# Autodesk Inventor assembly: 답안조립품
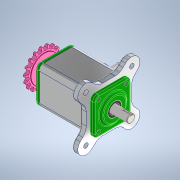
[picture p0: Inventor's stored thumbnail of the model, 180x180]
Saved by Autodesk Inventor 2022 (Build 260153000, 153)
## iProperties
Created: 2022-05
Part Number: 답안조립품
Document SubType Name: Assembly
Designer: Admin
Author: Admin
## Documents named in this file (11)
- C:\Users\Admin\Desktop\720509V1005\답안조립품.iam
- C:\Users\Admin\Desktop\720509V1005\본체.ipt
- C:\Users\Admin\Desktop\720509V1005\720509V1005\커버.ipt
- C:\Users\Admin\Desktop\720509V1005\720509V1005\베어링 6203.ipt
- C:\Users\Admin\Desktop\720509V1005\720509V1005\편심축.ipt
- C:\Users\Admin\Desktop\720509V1005\720509V1005\오일 실.ipt
- C:\Users\Admin\Desktop\720509V1005\720509V1005\부시.ipt
- C:\Users\Admin\Desktop\720509V1005\720509V1005\슬라이더.ipt
- C:\Users\Admin\Desktop\720509V1005\720509V1005\키 4 x 4 x 14.ipt
- C:\Users\Admin\Desktop\720509V1005\720509V1005\스프로킷.ipt
- C:\Users\Admin\Desktop\720509V1005\720509V1005\볼트 M4.ipt
